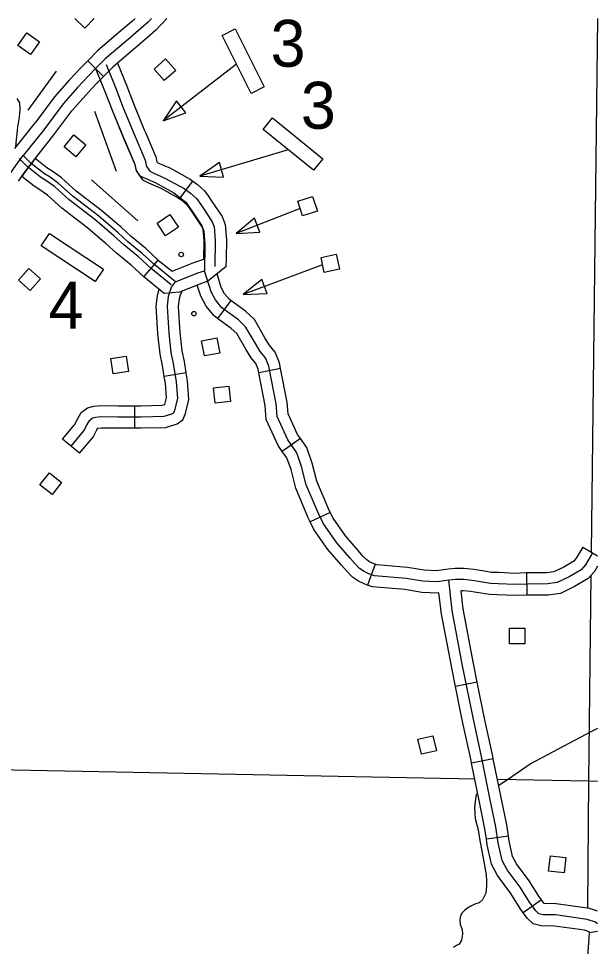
# Model space of a CAD drawing. Extents: x 61396 to 64680, y 55472 to 57605.
# Drawn here: x 63321.1 to 63443.1, y 56489.6 to 56685.3 of the extents above; entities that cross this region are included whole.
import ezdxf

# ---------------------------------------------------------------- set-up
doc = ezdxf.new("R2010")
doc.units = 0
for name, color, linetype in [('31', 7, 'Continuous'), ('32', 7, 'Continuous'), ('35', 7, 'Continuous'), ('45', 7, 'Continuous'), ('5', 7, 'Continuous'), ('56', 7, 'Continuous')]:
    doc.layers.add(name, color=color, linetype=linetype)

msp = doc.modelspace()

# ---------------------------------------------------------------- linework, layer by layer
at = {"layer": '31'}
for p, q in [((63339.02, 56673.08), (63335.68, 56676.37)), ((63338.32, 56672.37), (63339.02, 56673.08)), ((63328.53, 56660.77), (63328.53, 56660.77)), ((63322.37, 56652.84), (63325.22, 56656.57)), ((63355, 56647.26), (63357.81, 56651.01)), ((63347.49, 56630.81), (63350.55, 56634.36))]:
    msp.add_line(p, q, dxfattribs=at)
for points in [[(63349.14, 56685.27), (63348.41, 56684.5), (63343.79, 56680.52), (63339.35, 56676.76), (63337.35, 56674.73)], [(63345.71, 56685.27), (63345.24, 56684.86)], [(63352.39, 56685.27), (63350.02, 56682.8), (63348.3, 56681.31)], [(63345.24, 56684.86), (63342.27, 56682.3), (63337.75, 56678.48), (63335.68, 56676.37)], [(63348.3, 56681.31), (63345.32, 56678.73), (63341.95, 56675.89)], [(63335.68, 56676.37), (63334.23, 56674.9), (63331.8, 56672.29), (63328.7, 56668.78), (63324.79, 56663.59)], [(63341.95, 56675.89), (63340.94, 56675.04), (63340.1, 56674.18), (63339.02, 56673.08)], [(63339.54, 56675.6), (63341.5, 56670.74), (63343.14, 56666.48), (63345.44, 56660.91), (63347.8, 56655.41), (63348.06, 56654.1), (63348.8, 56653.07), (63349.46, 56652.74), (63352.11, 56651.58), (63356, 56649.43), (63357.32, 56648.44), (63358.52, 56647.41), (63359.02, 56646.74), (63359.93, 56645.42), (63361.92, 56642.44), (63362.33, 56641.33), (63362.58, 56638.56), (63362.48, 56632.99)], [(63341.95, 56675.89), (63343.68, 56671.6), (63345.32, 56667.35), (63347.6, 56661.82), (63347.85, 56661.22)], [(63337.35, 56674.73), (63335.93, 56673.28), (63333.53, 56670.72), (63330.51, 56667.3), (63326.18, 56661.54), (63322.09, 56656.4)], [(63337.35, 56674.73), (63339.31, 56669.86), (63340.95, 56665.6), (63343.25, 56660.03), (63345.61, 56654.53), (63345.87, 56653.22), (63346.61, 56652.19), (63347.27, 56651.86), (63349.92, 56650.7), (63353.81, 56648.55), (63355.13, 56647.56), (63356.33, 56646.53), (63356.83, 56645.87), (63357.74, 56644.54), (63359.73, 56641.57), (63360.14, 56640.45), (63360.39, 56637.68), (63360.29, 56632.11)], [(63336.53, 56670.49), (63337.62, 56671.66), (63339.02, 56673.08)], [(63338.32, 56672.37), (63339.32, 56669.88), (63340.96, 56665.61), (63343.27, 56660), (63343.54, 56659.37)], [(63328.53, 56660.77), (63332.33, 56665.82), (63335.27, 56669.14), (63336.53, 56670.49)], [(63324.79, 56663.59), (63324.33, 56662.98), (63320.26, 56657.86)], [(63325.22, 56656.57), (63328.03, 56660.11), (63328.53, 56660.77)], [(63347.85, 56661.22), (63350.05, 56656.11), (63350.26, 56655.06), (63350.36, 56654.91), (63350.46, 56654.86), (63353.15, 56653.69), (63357.28, 56651.4), (63357.81, 56651.01)], [(63343.54, 56659.37), (63345.55, 56654.71), (63345.86, 56653.13), (63347.24, 56651.23), (63348.47, 56650.62), (63351.07, 56649.48), (63354.72, 56647.46), (63355, 56647.26)], [(63319.26, 56652.44), (63320.51, 56654.27), (63322.09, 56656.4)], [(63354.17, 56629.78), (63349.9, 56633.25), (63347.24, 56635.69), (63344.16, 56638.2), (63342.03, 56640.15), (63338.03, 56643.58), (63332.61, 56647.73), (63329.53, 56650.52), (63327.76, 56651.8), (63326.59, 56652.5), (63323.76, 56654.73), (63322.09, 56656.4)], [(63353.3, 56629.12), (63349.02, 56632.59), (63346.36, 56635.03), (63343.28, 56637.54), (63341.16, 56639.49), (63337.16, 56642.93), (63331.74, 56647.07), (63328.66, 56649.86), (63326.88, 56651.14), (63325.72, 56651.85), (63322.88, 56654.08), (63321.21, 56655.75)], [(63324.57, 56655.73), (63322.37, 56652.84), (63321.77, 56651.97)], [(63329.4, 56652.22), (63328.18, 56653.1), (63327.05, 56653.78), (63324.57, 56655.73)], [(63321.06, 56650.95), (63322.37, 56652.84)], [(63327.18, 56648.04), (63325.59, 56649.18), (63324.38, 56649.92), (63321.77, 56651.97)], [(63342.28, 56641.62), (63338.63, 56644.75), (63333.24, 56648.87), (63330.13, 56651.69), (63329.4, 56652.22)], [(63357.81, 56651.01), (63358.79, 56650.27), (63360.25, 56649.01), (63360.92, 56648.11), (63361.87, 56646.73), (63364.02, 56643.51), (63364.64, 56641.85), (63364.92, 56638.64), (63364.86, 56634.74)], [(63339.23, 56638.06), (63335.68, 56641.1), (63330.23, 56645.27), (63327.18, 56648.04), (63326.66, 56648.41)], [(63360.17, 56634.54), (63360.23, 56638.47), (63360.02, 56640.81), (63359.81, 56641.37), (63357.99, 56644.11), (63357.12, 56645.38), (63356.8, 56645.8), (63355.85, 56646.61), (63355, 56647.26)], [(63350.55, 56634.36), (63347.9, 56636.8), (63344.82, 56639.32), (63342.71, 56641.25), (63342.28, 56641.62)], [(63347.49, 56630.81), (63344.83, 56633.26), (63341.75, 56635.77), (63339.6, 56637.74), (63339.23, 56638.06)], [(63350.55, 56634.36), (63353.45, 56632.02)], [(63353.45, 56632.02), (63358.08, 56633.85), (63360.17, 56634.54)], [(63364.86, 56634.74), (63364.83, 56632.95), (63361.03, 56629.89)], [(63351.82, 56627.3), (63347.49, 56630.81)], [(63354.17, 56629.78), (63358.88, 56631.64), (63360.29, 56632.11)], [(63354.17, 56629.78), (63358.88, 56631.64), (63360.29, 56632.11)], [(63361.03, 56629.89), (63359.68, 56629.44), (63355.03, 56627.6)], [(63355.03, 56627.6), (63351.82, 56627.3)]]:
    msp.add_lwpolyline(points, dxfattribs=at)
at = {"layer": '32'}
for p, q in [((63365.82, 56625.83), (63363.05, 56622.05)), ((63376.34, 56611.45), (63371.74, 56610.56)), ((63356.46, 56610.54), (63351.83, 56609.8)), ((63345.62, 56598.94), (63345.62, 56603.63)), ((63333.95, 56593.6), (63330.36, 56596.61)), ((63380.51, 56596.72), (63376.68, 56594.01)), ((63386.81, 56581.15), (63382.58, 56579.13)), ((63440.07, 56573.8), (63443.15, 56571.99)), ((63396.26, 56570.22), (63394.67, 56565.81)), ((63428.2, 56568.37), (63428.23, 56563.68)), ((63417.81, 56545.34), (63413.21, 56544.43)), ((63421.19, 56529.2), (63416.6, 56528.27)), ((63424.38, 56512.88), (63419.74, 56512.21)), ((63431.34, 56499.45), (63427.52, 56496.72)), ((63443.15, 56492.75), (63441.45, 56492.46))]:
    msp.add_line(p, q, dxfattribs=at)
for points in [[(63411.82, 56566.86), (63409.33, 56566.48), (63406.36, 56566.62), (63402.82, 56567.22), (63396.13, 56567.78), (63394.96, 56568.2), (63393.94, 56568.66), (63393.01, 56569.31), (63391.99, 56570.34), (63390.92, 56571.54), (63388.18, 56574.75), (63385.39, 56578.7), (63384.32, 56580.93), (63381.76, 56586.98), (63380.78, 56590.83), (63379.76, 56593.72), (63377.85, 56596.41), (63375.62, 56601.34), (63375.39, 56604.03), (63373.85, 56611.98), (63373.16, 56613.7), (63372.04, 56615.1), (63371.02, 56616.77), (63368.97, 56620.3), (63367.44, 56621.74), (63363.95, 56624.3), (63362.6, 56625.93), (63361.67, 56627.65), (63360.29, 56632.11)], [(63365.82, 56625.83), (63365.57, 56626.02), (63364.55, 56627.25), (63363.84, 56628.56), (63362.95, 56631.44)], [(63332.16, 56595.1), (63334.85, 56598.31), (63335.53, 56599.68), (63336.11, 56600.6), (63336.68, 56601.05), (63337.37, 56601.23), (63338.45, 56601.34), (63342.06, 56601.28), (63346.92, 56601.28), (63351.79, 56601.4), (63353.44, 56601.92), (63353.84, 56602.21), (63354.06, 56602.72), (63354.65, 56605.13), (63354.39, 56608.64), (63353.77, 56612.52), (63353.26, 56614.86), (63352.82, 56618.95), (63352.49, 56624.58), (63352.74, 56626.7), (63353.04, 56627.76), (63353.37, 56628.6), (63354.17, 56629.78)], [(63363.05, 56622.05), (63362.33, 56622.58), (63360.65, 56624.61), (63359.5, 56626.74), (63358.78, 56629.08)], [(63351.83, 56609.8), (63351.46, 56612.08), (63350.94, 56614.48), (63350.48, 56618.76), (63350.14, 56624.65), (63350.4, 56626.82)], [(63350.4, 56626.82), (63350.44, 56627.16), (63350.72, 56628.19)], [(63355.05, 56626.25), (63355.26, 56627.02), (63355.57, 56627.82)], [(63356.46, 56610.54), (63356.07, 56612.95), (63355.57, 56615.23), (63355.15, 56619.14), (63354.84, 56624.51), (63355.05, 56626.26)], [(63376.34, 56611.45), (63376.11, 56612.65), (63375.2, 56614.9), (63373.96, 56616.45), (63373.03, 56617.97), (63370.83, 56621.78), (63368.94, 56623.55), (63365.82, 56625.83)], [(63371.74, 56610.56), (63371.6, 56611.31), (63371.11, 56612.51), (63370.12, 56613.75), (63369, 56615.57), (63367.12, 56618.83), (63365.94, 56619.94), (63363.05, 56622.05)], [(63380.51, 56596.72), (63379.9, 56597.58), (63377.92, 56601.94), (63377.71, 56604.36), (63376.34, 56611.45)], [(63345.62, 56598.94), (63346.95, 56598.94), (63352.18, 56599.06), (63354.51, 56599.8), (63355.74, 56600.69), (63356.29, 56601.98), (63357.01, 56604.94), (63356.72, 56608.91), (63356.46, 56610.54)], [(63345.62, 56603.63), (63346.9, 56603.63), (63351.4, 56603.73), (63351.93, 56603.9), (63352.28, 56605.33), (63352.06, 56608.37), (63351.83, 56609.8)], [(63376.68, 56594.01), (63375.81, 56595.24), (63373.32, 56600.74), (63373.06, 56603.71), (63371.74, 56610.56)], [(63330.36, 56596.61), (63332.88, 56599.6), (63333.49, 56600.83), (63334.33, 56602.18), (63335.62, 56603.2), (63336.96, 56603.54), (63338.35, 56603.69), (63342.08, 56603.63), (63345.62, 56603.63)], [(63333.95, 56593.6), (63336.82, 56597.01), (63337.58, 56598.53), (63337.82, 56598.92), (63338.56, 56598.99), (63342.04, 56598.94), (63345.62, 56598.94)], [(63386.81, 56581.15), (63386.45, 56581.9), (63383.99, 56587.72), (63383.03, 56591.52), (63381.86, 56594.81), (63380.51, 56596.72)], [(63382.58, 56579.13), (63382.18, 56579.97), (63379.53, 56586.23), (63378.54, 56590.15), (63377.66, 56592.63), (63376.68, 56594.01)], [(63396.26, 56570.22), (63395.85, 56570.37), (63395.11, 56570.71), (63394.52, 56571.12), (63393.7, 56571.94), (63392.69, 56573.08), (63390.03, 56576.19), (63387.41, 56579.89), (63386.81, 56581.15)], [(63394.67, 56565.81), (63394.08, 56566.03), (63392.78, 56566.62), (63391.5, 56567.51), (63390.28, 56568.73), (63389.15, 56570.01), (63386.32, 56573.31), (63383.36, 56577.51), (63382.58, 56579.13)], [(63440.07, 56573.8), (63438.69, 56571.46), (63438.17, 56570.88), (63436.06, 56569.6), (63433.98, 56568.6), (63432.46, 56568.39), (63428.2, 56568.37)], [(63442.09, 56572.61), (63440.6, 56570.08), (63439.69, 56569.06), (63437.18, 56567.54), (63434.67, 56566.33), (63432.62, 56566.05), (63428.18, 56566.02), (63425.78, 56565.94), (63422.19, 56566.1), (63420.59, 56566.16), (63418.94, 56566.44), (63417.64, 56566.66), (63416.76, 56566.79), (63414.96, 56566.96), (63413.23, 56566.96), (63411.82, 56566.86)], [(63411.65, 56569.2), (63409.21, 56568.83), (63406.61, 56568.95), (63403.12, 56569.55), (63396.63, 56570.09), (63396.26, 56570.22)], [(63443.15, 56569.79), (63442.5, 56568.69), (63441.2, 56567.23), (63438.29, 56565.48), (63435.35, 56564.05), (63432.79, 56563.71), (63428.23, 56563.68)], [(63428.2, 56568.37), (63428.13, 56568.37), (63425.79, 56568.28), (63422.29, 56568.45), (63420.83, 56568.5), (63419.33, 56568.75), (63418.02, 56568.97), (63417.05, 56569.12), (63415.07, 56569.3), (63413.14, 56569.3), (63411.65, 56569.2)], [(63443.15, 56494.39), (63442.76, 56494.71), (63440.95, 56495.33), (63434.29, 56496.25), (63431.6, 56496.3), (63430.76, 56496.52), (63430.14, 56497.09), (63428.82, 56498.94), (63426.83, 56502.12), (63424.08, 56505.79), (63423.05, 56507.77), (63422.22, 56511.46), (63421.73, 56514.84), (63420.56, 56520.53), (63418.79, 56529.29), (63416.98, 56537.53), (63414.73, 56548.8), (63412.49, 56560.46), (63411.82, 56566.86)], [(63409.74, 56564.17), (63409.46, 56564.13), (63406.1, 56564.28), (63402.53, 56564.89), (63395.62, 56565.47), (63394.67, 56565.81)], [(63410.1, 56560.85), (63409.74, 56564.17)], [(63414.76, 56561.34), (63414.41, 56564.62)], [(63428.23, 56563.68), (63428.23, 56563.68), (63425.77, 56563.59), (63422.1, 56563.76), (63420.36, 56563.82), (63418.55, 56564.12), (63417.26, 56564.34), (63416.47, 56564.47), (63414.86, 56564.62), (63414.41, 56564.62)], [(63413.21, 56544.43), (63412.43, 56548.35), (63410.17, 56560.11), (63410.1, 56560.85)], [(63417.81, 56545.34), (63417.03, 56549.25), (63414.81, 56560.8), (63414.76, 56561.34)], [(63416.6, 56528.27), (63416.49, 56528.8), (63414.69, 56537.05), (63413.21, 56544.43)], [(63421.19, 56529.2), (63421.08, 56529.77), (63419.28, 56538.01), (63417.81, 56545.34)], [(63424.38, 56512.88), (63424.04, 56515.24), (63422.86, 56521), (63421.19, 56529.2)], [(63419.74, 56512.21), (63419.42, 56514.43), (63418.26, 56520.06), (63416.6, 56528.27)], [(63427.52, 56496.72), (63426.87, 56497.64), (63424.9, 56500.79), (63422.09, 56504.54), (63420.83, 56506.96), (63419.91, 56511.04), (63419.74, 56512.21)], [(63431.34, 56499.45), (63430.77, 56500.25), (63428.77, 56503.44), (63426.07, 56507.05), (63425.27, 56508.58), (63424.53, 56511.88), (63424.38, 56512.88)], [(63443.15, 56497.05), (63441.49, 56497.62), (63434.47, 56498.59), (63431.92, 56498.64), (63431.91, 56498.65), (63431.34, 56499.45)], [(63441.45, 56492.46), (63441.41, 56492.69), (63440.4, 56493.04), (63434.11, 56493.91), (63431.28, 56493.96), (63429.6, 56494.4), (63428.37, 56495.53), (63427.52, 56496.72)]]:
    msp.add_lwpolyline(points, dxfattribs=at)
at = {"layer": '35'}
for points in [[(63443.15, 56535.57), (63441.73, 56534.89), (63429.16, 56528.18), (63423.96, 56524.62), (63422.59, 56523.69), (63422.3, 56523.56)], [(63417.94, 56521.83), (63417.57, 56521.62), (63417.35, 56520.21), (63417.24, 56518.85), (63417.35, 56516.62), (63418, 56514.17), (63418.27, 56512.38)], [(63418.27, 56512.38), (63419.41, 56506.35), (63419.71, 56504.74), (63419.73, 56503.45), (63419.73, 56502.33), (63419.66, 56501.67), (63419.6, 56500.85), (63418.9, 56499.42), (63418.2, 56498.8), (63417.31, 56498.52), (63416.48, 56498.11), (63415.77, 56497.71), (63415.1, 56497.22), (63414.65, 56496.67), (63414.27, 56496.07), (63414.14, 56495.28), (63414.21, 56494.22), (63414.59, 56493.16), (63414.68, 56492.2), (63414.48, 56490.97), (63414.01, 56490.11), (63413.45, 56489.84), (63412.81, 56489.38)]]:
    msp.add_lwpolyline(points, dxfattribs=at)
at = {"layer": '45'}
for points in [[(63320.76, 56668.43), (63321.3, 56667.53), (63321.38, 56666.19), (63321.25, 56664.45), (63320.84, 56662.36), (63320.52, 56659.09), (63320.47, 56658.16)], [(63441.4, 56492.7), (63441.3, 56491.3), (63440.2, 56476.58)]]:
    msp.add_lwpolyline(points, dxfattribs=at)
at = {"layer": '5'}
for points in [[(63443.14, 56685.27), (63441.82, 56572.77)], [(63441.77, 56567.87), (63441.26, 56524.51)], [(63309.16, 56527.08), (63417.27, 56524.98)], [(63422.07, 56524.89), (63441.26, 56524.51)], [(63441.26, 56524.51), (63441.07, 56497.76)], [(63441.26, 56524.51), (63443.15, 56524.49)]]:
    msp.add_lwpolyline(points, dxfattribs=at)
at = {"layer": '56'}
for points in [[(63337.05, 56685.27), (63335.05, 56683.24), (63332.98, 56685.27)], [(63367.06, 56675.62), (63351.6, 56663.73)], [(63329, 56674.15), (63323.03, 56665.92)], [(63337.1, 56665.71), (63341.7, 56653.08)], [(63377.97, 56657.58), (63359.3, 56652.03)], [(63336.46, 56651.26), (63346.26, 56642.64)], [(63380.49, 56645.2), (63366.96, 56639.96)], [(63385.21, 56633.33), (63368.48, 56627.1)]]:
    msp.add_lwpolyline(points, dxfattribs=at)
for points in [[(63320.94, 56679.62), (63322.83, 56682.27), (63325.48, 56680.37), (63323.59, 56677.72)], [(63364, 56681.73), (63366.8, 56683.13), (63372.91, 56670.9), (63370.12, 56669.5)], [(63351.83, 56672.18), (63349.67, 56674.61), (63352.1, 56676.78), (63354.27, 56674.35)], [(63356.36, 56665.38), (63354.42, 56667.91), (63351.6, 56663.73)], [(63372.66, 56661.88), (63374.62, 56664.31), (63385.25, 56655.7), (63383.28, 56653.27)], [(63333.18, 56656.13), (63330.69, 56658.22), (63332.78, 56660.72), (63335.28, 56658.63)], [(63364.33, 56651.86), (63363.43, 56654.92), (63359.3, 56652.03)], [(63380.98, 56643.65), (63379.99, 56646.75), (63383.09, 56647.75), (63384.09, 56644.65)], [(63352.11, 56639.44), (63350.3, 56642.14), (63353.02, 56643.95), (63354.82, 56641.25)], [(63372, 56640.2), (63370.85, 56643.17), (63366.96, 56639.96)], [(63325.88, 56637.38), (63327.61, 56639.98), (63338.99, 56632.4), (63337.25, 56629.8)], [(63385.55, 56631.74), (63384.88, 56634.92), (63388.07, 56635.59), (63388.74, 56632.41)], [(63325.71, 56630.37), (63323.53, 56627.95), (63321.11, 56630.14), (63323.29, 56632.55)], [(63373.51, 56627.27), (63372.4, 56630.26), (63368.48, 56627.1)], [(63360.29, 56614.12), (63359.7, 56617.31), (63362.9, 56617.92), (63363.5, 56614.72)], [(63341.04, 56610.37), (63340.53, 56613.58), (63343.75, 56614.09), (63344.27, 56610.88)], [(63362.56, 56604.19), (63362.2, 56607.42), (63365.44, 56607.79), (63365.8, 56604.55)], [(63325.61, 56586.93), (63327.62, 56589.49), (63330.18, 56587.47), (63328.17, 56584.91)], [(63424.58, 56553.45), (63424.58, 56556.7), (63427.84, 56556.7), (63427.84, 56553.45)], [(63406.03, 56530.14), (63405.29, 56533.31), (63408.46, 56534.05), (63409.21, 56530.89)], [(63432.86, 56505.48), (63433.22, 56508.71), (63436.46, 56508.35), (63436.1, 56505.12)]]:
    msp.add_lwpolyline(points, close=True, dxfattribs=at)
for centre in [(63355.39, 56635.53), (63358.07, 56623.04)]:
    msp.add_circle(centre, 0.469, dxfattribs=at)

# ---------------------------------------------------------------- texts
for s, p in [('3', (63374.23, 56675.1)), ('3', (63380.62, 56662.04)), ('4', (63327.44, 56619.88))]:
    msp.add_text(s, height=9.9, dxfattribs=at).set_placement(p)

doc.saveas('drawing.dxf')
